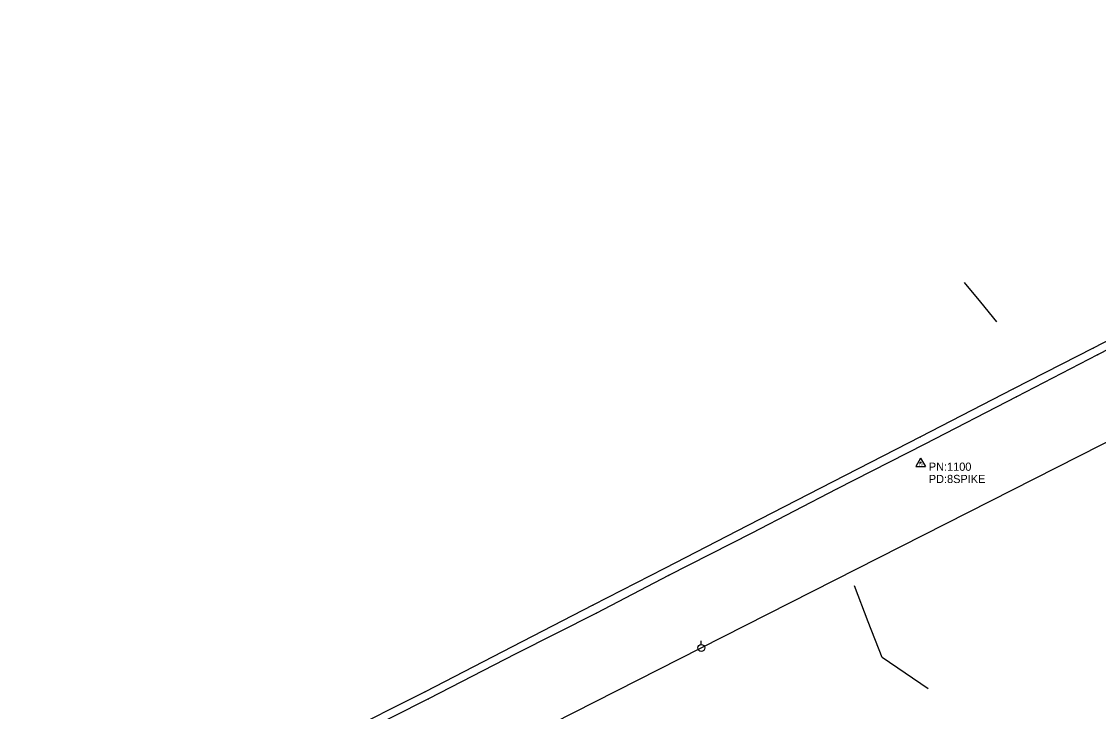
# Model space of a CAD drawing. Extents: x 1707085 to 1720058, y 548761 to 560063.
# Drawn here: x 1711331 to 1711989, y 549528 to 549950 of the extents above; entities that cross this region are included whole.
import ezdxf

# ---------------------------------------------------------------- set-up
doc = ezdxf.new("R2010")
doc.units = 0
for name, color, linetype in [('22', 7, 'Continuous'), ('R_Draft', 7, 'Continuous'), ('S_MSC_PT_SYM', 7, 'Continuous'), ('S_SECONDARY_CTL_ANNOT', 7, 'Continuous'), ('S_UTILITY_POLE', 7, 'Continuous')]:
    doc.layers.add(name, color=color, linetype=linetype)

msp = doc.modelspace()

# ---------------------------------------------------------------- linework, layer by layer
for points in [[(1711906.96, 549790.24), (1711916.77, 549778.23), (1711926.57, 549766.23)], [(1711884.86, 549541.91), (1711870.84, 549551.49), (1711856.83, 549561.08), (1711848.32, 549582.96), (1711839.82, 549604.84)]]:
    msp.add_lwpolyline(points)
at = {"layer": '22'}
for p, q in [((1712037.48, 549776.74), (1711985.75, 549750.13)), ((1712039.72, 549772.42), (1711988.25, 549745.9)), ((1711985.75, 549750.13), (1711936.64, 549724.94)), ((1711988.25, 549745.9), (1711938.75, 549720.42)), ((1711936.64, 549724.94), (1711880.28, 549695.93)), ((1711938.75, 549720.42), (1711882.84, 549691.43)), ((1711880.28, 549695.93), (1711826.66, 549668.39)), ((1711882.84, 549691.43), (1711828.89, 549663.84)), ((1711826.66, 549668.39), (1711774.75, 549641.75)), ((1711828.89, 549663.84), (1711777.21, 549637.14)), ((1711774.75, 549641.75), (1711723.93, 549615.52)), ((1711777.21, 549637.14), (1711726.24, 549611.1)), ((1711723.93, 549615.52), (1711680.17, 549593.11)), ((1711726.24, 549611.1), (1711682.3, 549588.16)), ((1711680.17, 549593.11), (1711630.86, 549567.64)), ((1711682.3, 549588.16), (1711633.14, 549563.43)), ((1711630.86, 549567.64), (1711577.67, 549540.23)), ((1711633.14, 549563.43), (1711579.84, 549535.89)), ((1711577.67, 549540.23), (1711523.96, 549513.27)), ((1711579.84, 549535.89), (1711526.2, 549508.94))]:
    msp.add_line(p, q, dxfattribs=at)
at = {"layer": 'R_Draft'}
for p, q in [((1711880.29, 549682.77), (1711877.28, 549677.82)), ((1711880.29, 549682.77), (1711883.24, 549677.82)), ((1711877.28, 549677.82), (1711883.24, 549677.82))]:
    msp.add_line(p, q, dxfattribs=at)
for radius in [0.311, 0.183, 0.103]:
    msp.add_circle((1711880.29, 549680.16), radius, dxfattribs=at)
at = {"layer": 'S_MSC_PT_SYM'}
for points in [[(1711985.75, 549750.13), (1711985.75, 549750.18), (1711985.75, 549750.13), (1711985.7, 549750.13), (1711985.75, 549750.13), (1711985.75, 549750.08), (1711985.75, 549750.13), (1711985.8, 549750.13)], [(1711988.25, 549745.9), (1711988.25, 549745.95), (1711988.25, 549745.9), (1711988.2, 549745.9), (1711988.25, 549745.9), (1711988.25, 549745.85), (1711988.25, 549745.9), (1711988.3, 549745.9)], [(1711936.64, 549724.94), (1711936.64, 549724.99), (1711936.64, 549724.94), (1711936.59, 549724.94), (1711936.64, 549724.94), (1711936.64, 549724.89), (1711936.64, 549724.94), (1711936.69, 549724.94)], [(1711938.75, 549720.42), (1711938.75, 549720.47), (1711938.75, 549720.42), (1711938.7, 549720.42), (1711938.75, 549720.42), (1711938.75, 549720.37), (1711938.75, 549720.42), (1711938.8, 549720.42)], [(1711880.28, 549695.93), (1711880.28, 549695.98), (1711880.28, 549695.93), (1711880.23, 549695.93), (1711880.28, 549695.93), (1711880.28, 549695.88), (1711880.28, 549695.93), (1711880.33, 549695.93)], [(1711882.84, 549691.43), (1711882.84, 549691.48), (1711882.84, 549691.43), (1711882.79, 549691.43), (1711882.84, 549691.43), (1711882.84, 549691.38), (1711882.84, 549691.43), (1711882.89, 549691.43)], [(1711826.66, 549668.39), (1711826.66, 549668.44), (1711826.66, 549668.39), (1711826.61, 549668.39), (1711826.66, 549668.39), (1711826.66, 549668.34), (1711826.66, 549668.39), (1711826.71, 549668.39)], [(1711828.89, 549663.84), (1711828.89, 549663.89), (1711828.89, 549663.84), (1711828.84, 549663.84), (1711828.89, 549663.84), (1711828.89, 549663.79), (1711828.89, 549663.84), (1711828.94, 549663.84)], [(1711774.75, 549641.75), (1711774.75, 549641.8), (1711774.75, 549641.75), (1711774.7, 549641.75), (1711774.75, 549641.75), (1711774.75, 549641.7), (1711774.75, 549641.75), (1711774.8, 549641.75)], [(1711777.21, 549637.14), (1711777.21, 549637.19), (1711777.21, 549637.14), (1711777.16, 549637.14), (1711777.21, 549637.14), (1711777.21, 549637.09), (1711777.21, 549637.14), (1711777.26, 549637.14)], [(1711723.93, 549615.52), (1711723.93, 549615.57), (1711723.93, 549615.52), (1711723.88, 549615.52), (1711723.93, 549615.52), (1711723.93, 549615.47), (1711723.93, 549615.52), (1711723.98, 549615.52)], [(1711726.24, 549611.1), (1711726.24, 549611.15), (1711726.24, 549611.1), (1711726.19, 549611.1), (1711726.24, 549611.1), (1711726.24, 549611.05), (1711726.24, 549611.1), (1711726.29, 549611.1)], [(1711680.17, 549593.11), (1711680.17, 549593.16), (1711680.17, 549593.11), (1711680.12, 549593.11), (1711680.17, 549593.11), (1711680.17, 549593.06), (1711680.17, 549593.11), (1711680.22, 549593.11)], [(1711682.3, 549588.16), (1711682.3, 549588.21), (1711682.3, 549588.16), (1711682.25, 549588.16), (1711682.3, 549588.16), (1711682.3, 549588.11), (1711682.3, 549588.16), (1711682.35, 549588.16)], [(1711630.86, 549567.64), (1711630.86, 549567.69), (1711630.86, 549567.64), (1711630.81, 549567.64), (1711630.86, 549567.64), (1711630.86, 549567.59), (1711630.86, 549567.64), (1711630.91, 549567.64)], [(1711633.14, 549563.43), (1711633.14, 549563.48), (1711633.14, 549563.43), (1711633.09, 549563.43), (1711633.14, 549563.43), (1711633.14, 549563.38), (1711633.14, 549563.43), (1711633.19, 549563.43)], [(1711577.67, 549540.23), (1711577.67, 549540.28), (1711577.67, 549540.23), (1711577.62, 549540.23), (1711577.67, 549540.23), (1711577.67, 549540.18), (1711577.67, 549540.23), (1711577.72, 549540.23)], [(1711579.84, 549535.89), (1711579.84, 549535.94), (1711579.84, 549535.89), (1711579.79, 549535.89), (1711579.84, 549535.89), (1711579.84, 549535.84), (1711579.84, 549535.89), (1711579.89, 549535.89)]]:
    msp.add_lwpolyline(points, dxfattribs=at)
at = {"layer": 'S_UTILITY_POLE'}
msp.add_line((1711746.21, 549569.1), (1711746.21, 549571.21), dxfattribs=at)
msp.add_lwpolyline([(1711064.39, 549251.72), (1711313.01, 549347.35), (1711526.73, 549455.46), (1711746.33, 549566.96), (1712411.7, 549904.79), (1712500.91, 549949.57)], dxfattribs=at)
msp.add_circle((1711746.33, 549566.96), 2.13, dxfattribs=at)

# ---------------------------------------------------------------- texts
at = {"layer": 'R_Draft'}
msp.add_text('TV', height=1.5, rotation=360, dxfattribs=at).set_placement((1711879.08, 549678.15))
at = {"layer": 'S_SECONDARY_CTL_ANNOT'}
for s, p in [('PN:1100', (1711885.29, 549675.16)), ('PD:8SPIKE', (1711885.29, 549667.66))]:
    msp.add_text(s, height=5, dxfattribs=at).set_placement(p)

doc.saveas('drawing.dxf')
